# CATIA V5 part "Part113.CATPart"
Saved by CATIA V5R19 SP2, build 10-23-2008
Part number: Part13
Bounding box of the stored display mesh (mm): x -142.872 to -91.2, y -157.712 to -136.967, z 36.512 to 68.489
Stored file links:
  C:\BEHROOZ\catia learning\tarh haye mashin\hb\Part113.CATPart
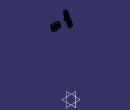
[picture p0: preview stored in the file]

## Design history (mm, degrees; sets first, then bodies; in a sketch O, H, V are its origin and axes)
Body1 (main body)
  Plane1: stored without definition
  DatumSurface1
  Sketch1 on Plane1, origin (-162.665, 0, 0), H (0, 1, 0), V (0, 0, 1)
    line L1 (-137.2417, 35.4511) -> (-155.9918, 69.4793)
    line L2 (-155.9918, 69.4793) -> (-154.5844, 69.4793)
    line L3 (-154.5844, 69.4793) -> (-135.8344, 35.4511)
    line L4 (-135.8344, 35.4511) -> (-137.2417, 35.4511)
  Pad1: profile Sketch1, direction (1, 0, 0), length 127, opposite side length -18
  Sketch2 on face of Pad1 from Sketch1.L3, origin (0, -84.162, -58.3256), H (-1, 0, 0), V (0, -0.4826, 0.8758)
    line L1 (138.8715, 108.9615) -> (135.5312, 108.9615)
    line L2 (131.5312, 112.9615) -> (131.5312, 141.0426)
    line L3 (135.5312, 145.0426) -> (138.8715, 145.0426)
    line L4 (142.8715, 141.0426) -> (142.8715, 112.9615)
    line L5 (110.1609, 117.6007) -> (95.2003, 117.6007)
    line L6 (91.2003, 121.6007) -> (91.2003, 129.1415)
    line L7 (95.2003, 133.1415) -> (110.1609, 133.1415)
    line L8 (114.1609, 129.1415) -> (114.1609, 121.6007)
    line L9 (165.9962, 156.5915) -> (24.7331, 156.5915)
    line L10 (24.7331, 156.5915) -> (24.7331, 91.3129)
    line L11 (24.7331, 91.3129) -> (165.9962, 91.3129)
    line L12 (165.9962, 91.3129) -> (165.9962, 156.5915)
    arc A1 centre (138.8715, 112.9615) radius 4 from (142.8715, 112.9615) to (138.8715, 108.9615) cw
    arc A2 centre (135.5312, 112.9615) radius 4 from (131.5312, 112.9615) to (135.5312, 108.9615) ccw
    arc A3 centre (135.5312, 141.0426) radius 4 from (135.5312, 145.0426) to (131.5312, 141.0426) ccw
    arc A4 centre (138.8715, 141.0426) radius 4 from (142.8715, 141.0426) to (138.8715, 145.0426) ccw
    arc A5 centre (110.1609, 121.6007) radius 4 from (114.1609, 121.6007) to (110.1609, 117.6007) cw
    arc A6 centre (95.2003, 121.6007) radius 4 from (91.2003, 121.6007) to (95.2003, 117.6007) ccw
    arc A7 centre (95.2003, 129.1415) radius 4 from (95.2003, 133.1415) to (91.2003, 129.1415) ccw
    arc A8 centre (110.1609, 129.1415) radius 4 from (114.1609, 129.1415) to (110.1609, 133.1415) ccw
  Pocket1: profile Sketch2, direction (0, -0.8758, -0.4826), length 127
  Sketch3 on face of Pad1 from Sketch1.L3, origin (0, -89.2135, -49.158), H (-1, 0, 0), V (0, -0.4826, 0.8758)
    line L1 (133.5525, 131.9523) -> (133.5525, 101.609)
    line L2 (135.955, 131.9523) -> (135.955, 101.609)
    line L3 (138.3575, 131.9523) -> (138.3575, 101.609)
    line L4 (140.76, 131.9523) -> (140.76, 101.609)
    line L5 (111.6628, 119.4947) -> (111.6628, 110.4184)
    line L6 (108.1036, 119.4947) -> (108.1036, 110.4184)
    line L7 (104.5444, 119.4947) -> (104.5444, 110.4184)
    line L8 (100.9851, 119.4947) -> (100.9851, 110.4184)
    line L9 (97.4259, 119.4947) -> (97.4259, 110.4184)
    line L10 (93.8667, 119.4947) -> (93.8667, 110.4184)
    line L11 (72.6284, 119.4947) -> (72.6284, 110.4184)
    line L12 (69.0692, 119.4947) -> (69.0692, 110.4184)
    line L13 (65.51, 119.4947) -> (65.51, 110.4184)
    line L14 (61.9507, 119.4947) -> (61.9507, 110.4184)
    line L15 (58.3915, 119.4947) -> (58.3915, 110.4184)
    line L16 (54.8323, 119.4947) -> (54.8323, 110.4184)
  Pocket2: profile Sketch3, direction (0, -0.8758, -0.4826), length 1, thin wall 0.5, second thickness 0.5
  Fillet1: radius 0.6, on face of Pad1 from Sketch1.L3 (x2)
Body2
  Plane2: stored without definition
  Sketch4 on Plane2, origin (-162.665, 0, 0), H (0, 1, 0), V (0, 0, 1)
    arc A1 centre (-162.4018, 65.6741) radius 19.6825 from (-146.6615, 53.8572) to (-160.1599, 46.1198) cw
    line L1 (-160.1599, 46.1198) -> (-159.3356, 43.8117)
    arc A2 centre (-162.2265, 65.8536) radius 22.2306 from (-159.3356, 43.8117) to (-145.3186, 51.4201) ccw
    line L2 (-145.3186, 51.4201) -> (-146.6615, 53.8572)
  Pad2: profile Sketch4, direction (1, 0, 0), length 21, opposite side length -102
  DatumSurface2
  Sketch5 on face of Pad2 from Sketch4.L2, origin (0, -89.739, -49.4475), H (-1, 0, 0), V (0, -0.4826, 0.8758)
    line L1 (135.3351, 118.4308) -> (138.9379, 118.4308)
    line L2 (138.9379, 118.4308) -> (138.9379, 114.7135)
    line L3 (138.9379, 114.7135) -> (135.3351, 114.7135)
    line L4 (135.3351, 114.7135) -> (135.3351, 118.4308)
    line L5 (100.9107, 118.8074) -> (104.8816, 118.8074)
    line L6 (104.8816, 118.8074) -> (104.8816, 113.934)
    line L7 (104.8816, 113.934) -> (100.9107, 113.934)
    line L8 (100.9107, 113.934) -> (100.9107, 118.8074)
    line L9 (167.8334, 138.3229) -> (37.1452, 138.3229)
    line L10 (37.1452, 138.3229) -> (37.1452, 95.9972)
    line L11 (37.1452, 95.9972) -> (167.8334, 95.9972)
    line L12 (167.8334, 95.9972) -> (167.8334, 138.3229)
  Pocket3: profile Sketch5, direction (0, -0.8758, -0.4826), length 54
  Split1: SplitPlane DatumSurface2
  Split2: SplitPlane face of Pad1 from Sketch1.L1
